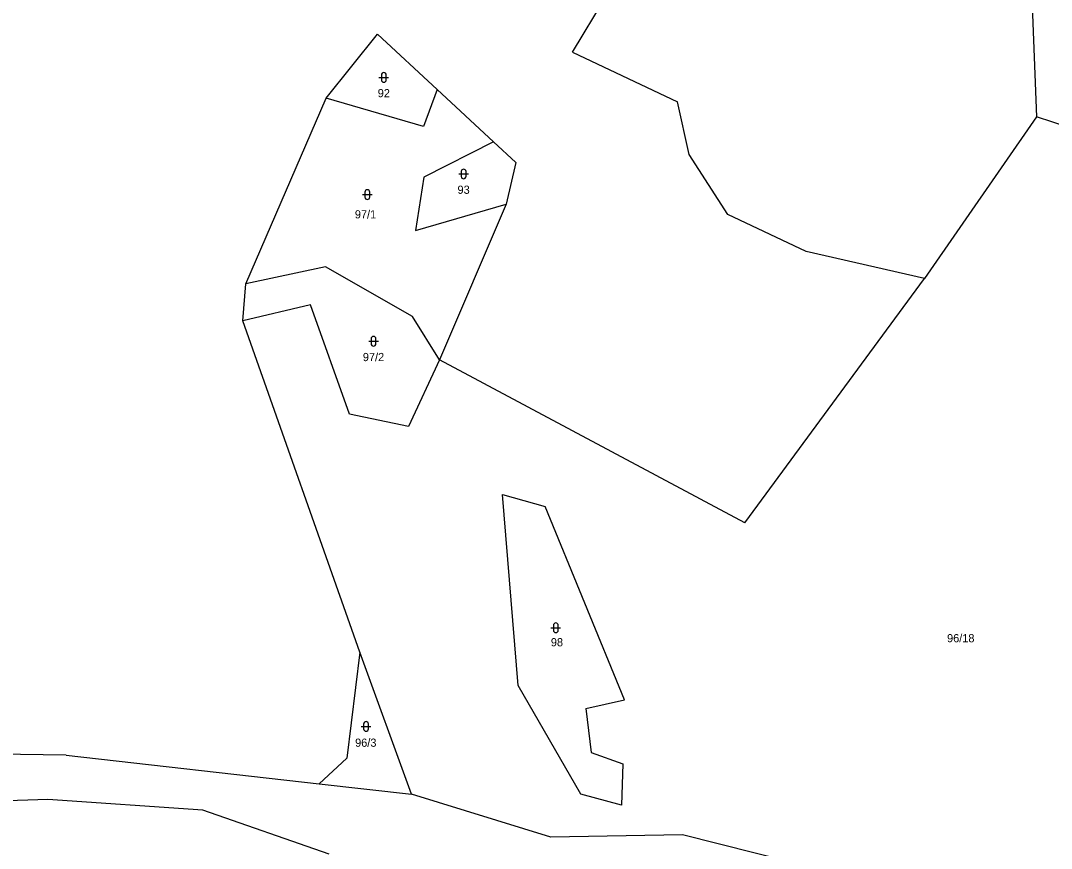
# Model space of a CAD drawing. Extents: x -765428 to -762163, y -1107632 to -1104975.
# Drawn here: x -763790.9 to -763576.9, y -1106028 to -1105856 of the extents above; entities that cross this region are included whole.
import ezdxf
from ezdxf.enums import TextEntityAlignment as Align

# ---------------------------------------------------------------- set-up
doc = ezdxf.new("R2010")
doc.units = 0
doc.header["$LTSCALE"] = 0.68
doc.layers.add('1', color=7, linetype='Continuous', lineweight=25)
doc.layers.add('3', color=7, linetype='Continuous', lineweight=25)
doc.layers.add('2', color=7, linetype='Continuous')

msp = doc.modelspace()

# ---------------------------------------------------------------- linework, layer by layer
at = {"layer": '1'}
for p, q in [((-763676.35, -1105862.56), (-763639.64, -1105801.86)), ((-763581.41, -1105839.04), (-763579.97, -1105876.02)), ((-763727.45, -1105872.16), (-763716.83, -1105858.82)), ((-763716.83, -1105858.82), (-763704.42, -1105870.34)), ((-763676.35, -1105862.56), (-763654.54, -1105872.92)), ((-763704.42, -1105870.34), (-763707.29, -1105878.02)), ((-763704.42, -1105870.34), (-763692.7, -1105881.22)), ((-763744.17, -1105910.74), (-763727.45, -1105872.16)), ((-763707.29, -1105878.02), (-763727.45, -1105872.16)), ((-763652.1, -1105883.81), (-763654.54, -1105872.92)), ((-763579.97, -1105876.02), (-763603.25, -1105909.6)), ((-763573.18, -1105878.25), (-763579.97, -1105876.02)), ((-763692.7, -1105881.22), (-763688.12, -1105885.47)), ((-763688.12, -1105885.47), (-763690.07, -1105894.16)), ((-763644.09, -1105896.31), (-763652.1, -1105883.81)), ((-763708.93, -1105899.6), (-763690.07, -1105894.16)), ((-763690.07, -1105894.16), (-763703.95, -1105926.47)), ((-763627.8, -1105904), (-763644.09, -1105896.31)), ((-763603.25, -1105909.6), (-763627.8, -1105904)), ((-763727.65, -1105907.17), (-763744.17, -1105910.74)), ((-763709.53, -1105917.47), (-763727.65, -1105907.17)), ((-763744.76, -1105918.36), (-763744.17, -1105910.74)), ((-763640.53, -1105960.38), (-763603.25, -1105909.6)), ((-763730.75, -1105915.06), (-763744.76, -1105918.36)), ((-763722.64, -1105937.77), (-763730.75, -1105915.06)), ((-763703.95, -1105926.47), (-763709.53, -1105917.47)), ((-763720.52, -1105987.23), (-763744.76, -1105918.36)), ((-763703.95, -1105926.47), (-763710.36, -1105940.38)), ((-763640.53, -1105960.38), (-763703.95, -1105926.47)), ((-763710.36, -1105940.38), (-763722.64, -1105937.77)), ((-763690.85, -1105954.48), (-763682.02, -1105956.94)), ((-763687.63, -1105994.16), (-763690.85, -1105954.48)), ((-763665.55, -1105997.15), (-763682.02, -1105956.94)), ((-763720.52, -1105987.23), (-763723.2, -1106009.25)), ((-763709.76, -1106016.76), (-763720.52, -1105987.23)), ((-763674.57, -1106016.71), (-763687.63, -1105994.16)), ((-763673.58, -1105998.92), (-763665.55, -1105997.15)), ((-763673.58, -1105998.92), (-763672.46, -1106008.09)), ((-763781.46, -1106008.6), (-763805.07, -1106008.32)), ((-763781.46, -1106008.6), (-763728.92, -1106014.58)), ((-763723.2, -1106009.25), (-763728.92, -1106014.58)), ((-763672.46, -1106008.09), (-763665.89, -1106010.41)), ((-763665.89, -1106010.41), (-763666.12, -1106019)), ((-763728.92, -1106014.58), (-763709.76, -1106016.76)), ((-763785.27, -1106017.82), (-763837.47, -1106019.51)), ((-763753.11, -1106020.03), (-763785.27, -1106017.82)), ((-763680.79, -1106025.65), (-763709.76, -1106016.76)), ((-763666.12, -1106019), (-763674.57, -1106016.71)), ((-763726.87, -1106029.18), (-763753.11, -1106020.03)), ((-763653.49, -1106025.2), (-763680.79, -1106025.65)), ((-763616.09, -1106034.57), (-763653.49, -1106025.2))]:
    msp.add_line(p, q, dxfattribs=at)
msp.add_lwpolyline([(-763692.7, -1105881.22), (-763707.2, -1105888.58), (-763708.93, -1105899.6)], dxfattribs=at)
at = {"layer": '3'}
for p, q in [((-763716.511, -1105867.821), (-763714.509, -1105867.821)), ((-763716.011, -1105867.321), (-763716.011, -1105868.322)), ((-763715.009, -1105868.322), (-763715.009, -1105867.321)), ((-763699.441, -1105887.381), (-763699.441, -1105888.382)), ((-763698.439, -1105888.382), (-763698.439, -1105887.381)), ((-763699.941, -1105887.881), (-763697.939, -1105887.881)), ((-763719.431, -1105891.671), (-763719.431, -1105892.672)), ((-763718.429, -1105892.672), (-763718.429, -1105891.671)), ((-763719.931, -1105892.171), (-763717.929, -1105892.171)), ((-763718.651, -1105922.641), (-763716.649, -1105922.641)), ((-763718.151, -1105922.141), (-763718.151, -1105923.142)), ((-763717.149, -1105923.142), (-763717.149, -1105922.141)), ((-763680.291, -1105981.671), (-763680.291, -1105982.672)), ((-763679.289, -1105982.672), (-763679.289, -1105981.671)), ((-763680.791, -1105982.171), (-763678.789, -1105982.171)), ((-763720.201, -1106002.651), (-763718.199, -1106002.651)), ((-763719.701, -1106002.151), (-763719.701, -1106003.152)), ((-763718.699, -1106003.152), (-763718.699, -1106002.151))]:
    msp.add_line(p, q, dxfattribs=at)
for centre, start, end in [((-763715.51, -1105867.3209), 0, 180), ((-763715.51, -1105868.3209), 180, 359.98789), ((-763698.94, -1105887.3809), 0, 180), ((-763698.94, -1105888.3809), 180, 359.98789), ((-763718.93, -1105891.6709), 0, 180), ((-763718.93, -1105892.6709), 180, 359.98789), ((-763717.65, -1105922.1409), 0, 180), ((-763717.65, -1105923.1409), 180, 359.98789), ((-763679.79, -1105981.6709), 0, 180), ((-763679.79, -1105982.6709), 180, 359.98789), ((-763719.2, -1106002.1509), 0, 180), ((-763719.2, -1106003.1509), 180, 359.98789)]:
    msp.add_arc(centre, 0.5, start, end, dxfattribs=at)

# ---------------------------------------------------------------- texts
at = {"layer": '2'}
for s, p in [('92', (-763715.509, -1105871.945)), ('93', (-763698.939, -1105892.005)), ('97/1', (-763719.309, -1105897.115)), ('97/2', (-763717.649, -1105926.765)), ('96/18', (-763595.69, -1105985.175))]:
    msp.add_text(s, height=1.7, dxfattribs=at).set_placement(p, align=Align.CENTER)
for s, p in [('98', (-763680.82, -1105986.015)), ('96/3', (-763721.47, -1106006.885))]:
    msp.add_text(s, height=1.7, dxfattribs=at).set_placement(p)

doc.saveas('drawing.dxf')
